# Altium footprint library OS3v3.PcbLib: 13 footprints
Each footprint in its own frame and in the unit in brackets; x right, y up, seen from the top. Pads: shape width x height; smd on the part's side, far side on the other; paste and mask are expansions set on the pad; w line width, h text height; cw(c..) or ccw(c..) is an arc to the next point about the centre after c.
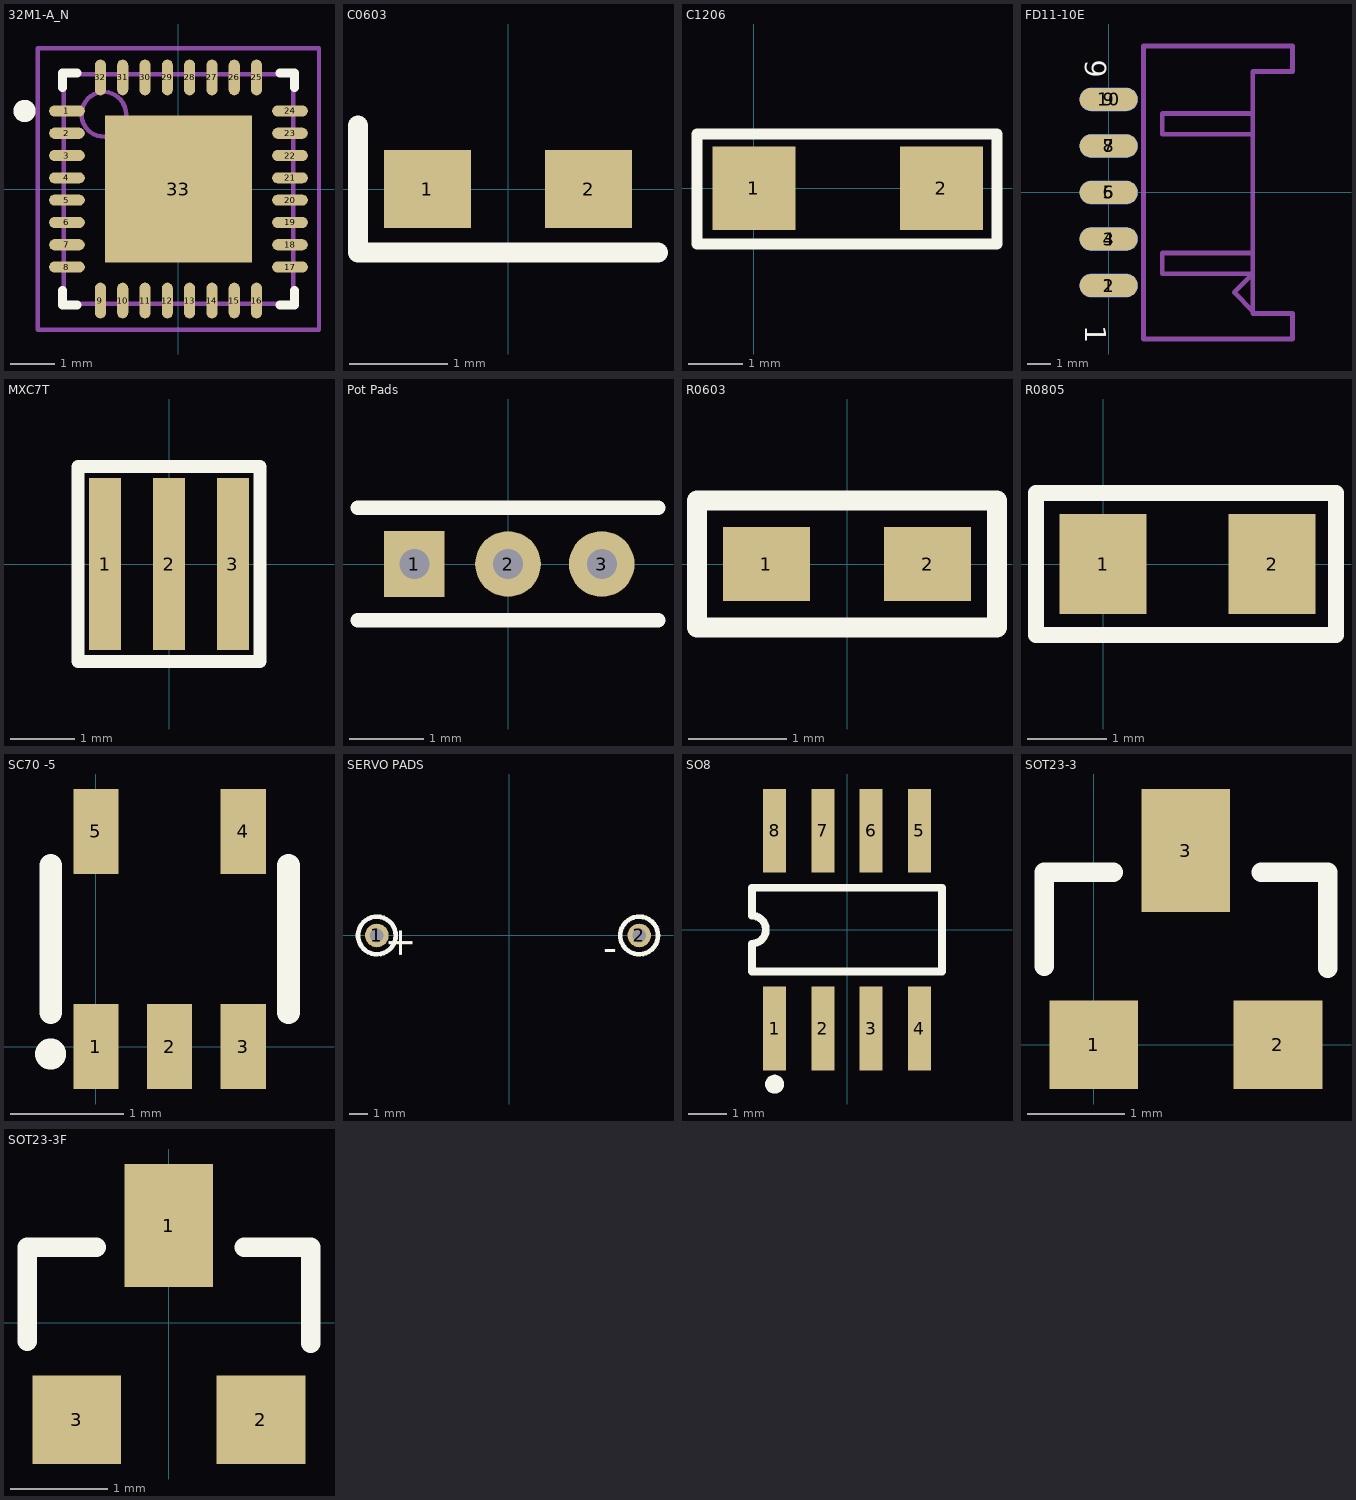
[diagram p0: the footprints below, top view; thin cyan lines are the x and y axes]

## 32M1-A_N [mm] "QFN, 32-Leads, Body 5x5mm, Pitch 0.5mm, IPC Medium Density"
height 1
pads (33):
  oval 0.8x0.25 smd: 1(-2.5,1.75) 2(-2.5,1.25) 3(-2.5,0.75) 4(-2.5,0.25) 5(-2.5,-0.25) 6(-2.5,-0.75) 7(-2.5,-1.25) 8(-2.5,-1.75) 17(2.5,-1.75) 18(2.5,-1.25) 19(2.5,-0.75) 20(2.5,-0.25) 21(2.5,0.25) 22(2.5,0.75) 23(2.5,1.25) 24(2.5,1.75)
  oval 0.25x0.8 smd: 9(-1.75,-2.5) 10(-1.25,-2.5) 11(-0.75,-2.5) 12(-0.25,-2.5) 13(0.25,-2.5) 14(0.75,-2.5) 15(1.25,-2.5) 16(1.75,-2.5) 25(1.75,2.5) 26(1.25,2.5) 27(0.75,2.5) 28(0.25,2.5) 29(-0.25,2.5) 30(-0.75,2.5) 31(-1.25,2.5) 32(-1.75,2.5)
  rect 3.3x3.3 smd: 33(0,0)
Top Overlay:
  circle w0.25: c-3.45,1.75 r0.125
  lines w0.2: -2.6,-2.275 -2.6,-2.6 -2.275,-2.6 ; -2.6,2.275 -2.6,2.6 -2.275,2.6 ; 2.275,-2.6 2.6,-2.6 2.6,-2.275 ; 2.275,2.6 2.6,2.6 2.6,2.275
Mechanical 13:
  circle w0.1: c-1.675,1.675 r0.5
  lines w0.1: -2.575,-2.575 2.575,-2.575 2.575,2.575 -2.575,2.575 -2.575,-2.575
Mechanical 15:
  lines w0.1: -0.5,0 0.5,0 ; 0,-0.5 0,0.5 ; -3.15,-3.15 3.15,-3.15 3.15,3.15 -3.15,3.15 -3.15,-3.15
3D body: height 1, standoff 0, extent -2.575,-2.575 2.575,2.575

## C0603 [mm]
height 0.254
pads (2):
  rect 0.89x0.8 smd: 1(-0.825,0) 2(0.825,0)
Top Overlay:
  lines w0.203: -1.535,0.65 -1.535,-0.65 1.535,-0.65

## C1206 [mil]
pads (2):
  rect 60x60 smd: 1(0,0) 2(135,0)
Top Overlay:
  lines w8: -41,-40 -41,39 175,39 175,-40 -41,-40

## FD11-10E [mm] "Hirose 2mm, 10 pin, TH, Edge Application"
height 2.5
pads (10):
  oval 2.5x1 smd: 1(0,-4) 3(0,-2) 5(0,0) 7(0,2) 9(0,4)
  oval 2.5x1 smd far side: 2(0,-4) 4(0,-2) 6(0,0) 8(0,2) 10(0,4)
Top Overlay:
  text "1" at -1.016,-5.719 h0.89
  text "9" at -1.016,5.711 h0.89
Bottom Overlay:
  text "2" at -1.143,-6.1 h0.89
  text "10" at -1.016,4.695 h0.89
Mechanical 5:
  lines w0.203: 6.2,-5.1 5.4,-4.3 6.2,-3.5 2.3,-3.5 2.3,-2.6 6.2,-2.6 ; 6.2,2.5 2.3,2.5 2.3,3.4 6.2,3.4 ; 1.5,-6.3 1.5,6.3 7.9,6.3 7.9,5.2 6.2,5.2 6.2,-5.2 7.9,-5.2 7.9,-6.3 1.5,-6.3

## MXC7T [mm] "TDK Ceramic Resonator"
height 1
pads (3):
  rect 0.5x2.7 smd: 1(-1,0) 2(0,0) 3(1,0)
Top Overlay:
  lines w0.203: -1.425,-1.525 1.425,-1.525 1.425,1.525 -1.425,1.525 -1.425,-1.525

## Pot Pads [mil]
height 10
pads (3):
  rect 32x35 hole 16: 1(-50,0)
  round 35 hole 16: 2(0,0) 3(50,0)
Top Overlay:
  lines w7.99: -80,-30 80,-30 ; -80,30 80,30

## R0603 [mm]
height 0.254
pads (2):
  rect 0.89x0.76 smd: 1(-0.825,0) 2(0.825,0)
Top Overlay:
  lines w0.2: -1.535,-0.65 -1.535,0.65 1.535,0.65 1.535,-0.65 -1.535,-0.65

## R0805 [mm]
height 0.254
pads (2):
  rect 1.1x1.27 smd: 1(0,0) 2(2.14,0)
Top Overlay:
  lines w0.203: -0.85,-0.9 2.95,-0.9 2.95,0.9 -0.85,0.9 -0.85,-0.9

## SC70 -5 [mm]
height 1.016
pads (5):
  rect 0.4x0.75 smd: 1(0,0) 2(0.65,0) 3(1.3,0) 4(1.3,1.9) 5(0,1.9)
Top Overlay:
  circle w0.254: c-0.4,-0.066 r0.01
  lines w0.2: -0.4,0.3 -0.4,1.6 ; 1.7,0.3 1.7,1.6

## SERVO PADS [mm]
pads (2):
  round 1.27 hole 0.737: 1(-7.12,0) 2(7.02,0)
Top Overlay:
  circle w0.254: c-7.12,0 r1.016
  circle w0.254: c7.01,0 r1.016
  text "-" at 5.842,-1.397 h1.52
  text "+" at -6.477,-1.27 h1.52

## SO8 [mm] "Small Outline; 8 Leads; Body Width 3.9 mm; Pitch 1.27 mm"
height 1.75
pads (8):
  rect 0.6x2.2 smd: 1(-1.905,-2.6) 2(-0.635,-2.6) 3(0.635,-2.6) 4(1.905,-2.6) 5(1.905,2.6) 6(0.635,2.6) 7(-0.635,2.6) 8(-1.905,2.6)
Top Overlay:
  circle w0.25: c-1.905,-4.066 r0.125
  lines w0.2: -2.5,-1.1 2.5,-1.1 2.5,1.1 -2.5,1.1 -2.5,0.367 cw(c-2.5,0) -2.5,-0.367 -2.5,-1.1

## SOT23-3 [mm]
height 0.254
pads (3):
  rect 0.914x0.914 smd: 1(0,0) 2(1.9,0)
  rect 0.914x1.27 smd: 3(0.95,2)
Top Overlay:
  lines w0.203: -0.508,0.807 -0.508,1.778 0.203,1.778 ; 1.727,1.778 2.413,1.778 2.413,0.787

## SOT23-3F [mm] "Zetex cw pin numbers"
height 1.1
pads (3):
  rect 0.914x1.27 smd: 1(0,1)
  rect 0.914x0.914 smd: 2(0.95,-1) 3(-0.95,-1)
Top Overlay:
  lines w0.203: -1.458,-0.193 -1.458,0.778 -0.747,0.778 ; 0.777,0.778 1.463,0.778 1.463,-0.213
